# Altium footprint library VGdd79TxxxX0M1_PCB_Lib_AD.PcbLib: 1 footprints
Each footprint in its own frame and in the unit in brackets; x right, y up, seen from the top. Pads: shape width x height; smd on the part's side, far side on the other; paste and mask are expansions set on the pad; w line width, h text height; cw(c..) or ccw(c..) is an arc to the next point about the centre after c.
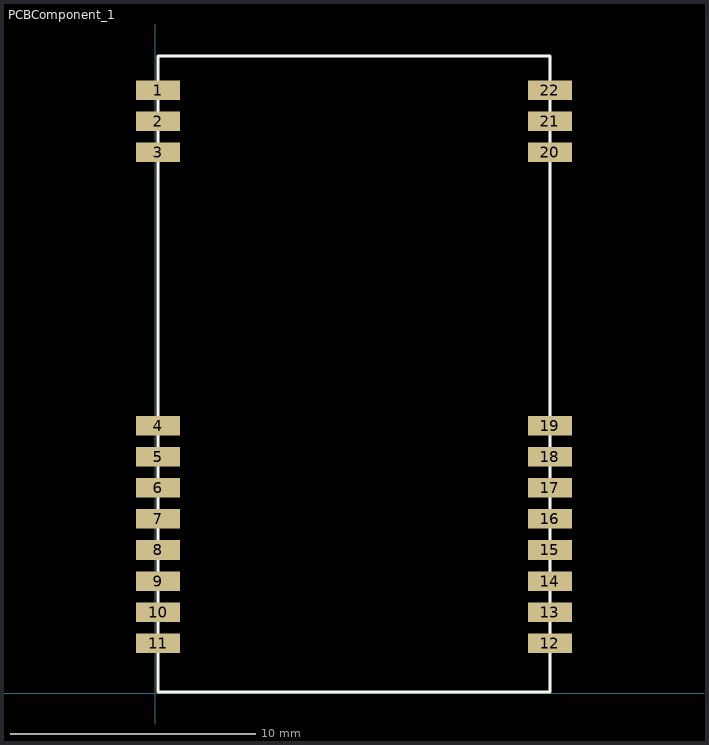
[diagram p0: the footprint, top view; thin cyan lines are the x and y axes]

## PCBComponent_1 [mm]
pads (22):
  rect 1.8x0.8 smd: 1(0.128,24.635) 2(0.128,23.365) 3(0.128,22.095) 4(0.128,10.925) 5(0.128,9.655) 6(0.128,8.385) 7(0.128,7.115) 8(0.128,5.845) 9(0.128,4.575) 10(0.128,3.305) 11(0.128,2.035) 12(16.128,2.035) 13(16.128,3.305) 14(16.128,4.575) 15(16.128,5.845) 16(16.128,7.115) 17(16.128,8.385) 18(16.128,9.655) 19(16.128,10.925) 20(16.128,22.095) 21(16.128,23.365) 22(16.128,24.635)
Top Overlay:
  lines w0.025: 0.128,0.035 0.128,26.035
  lines w0.127: 0.128,0.035 0.128,26.035 16.128,26.035 16.128,22.095 16.128,0.035 0.128,0.035
Mechanical 5:
  lines w0.025: 0.128,0.035 16.128,0.035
